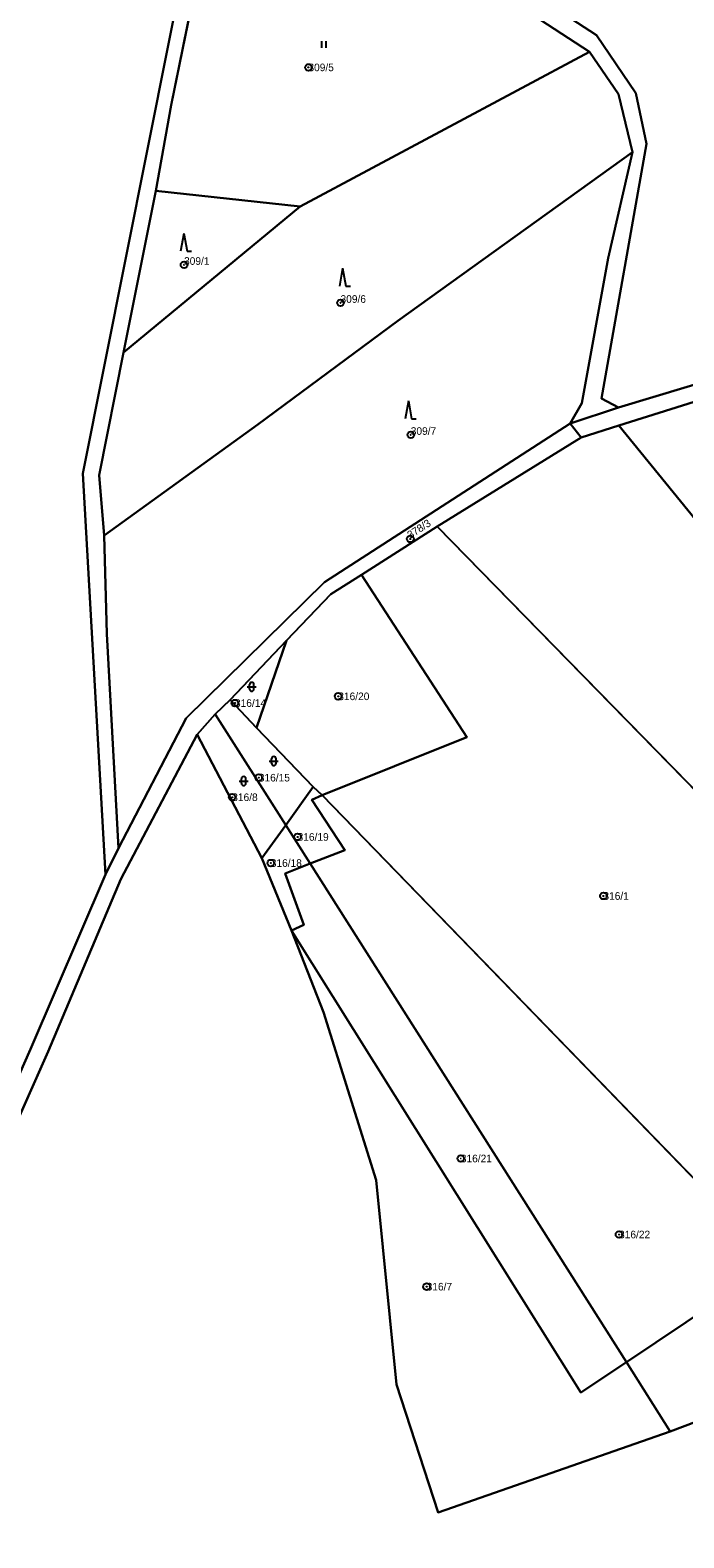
# Model space of a CAD drawing. Extents: x -652854 to -650068, y -1097661 to -1095417.
# Drawn here: x -651296.9 to -651150.7, y -1097423.6 to -1097086.2 of the extents above; entities that cross this region are included whole.
import ezdxf

# ---------------------------------------------------------------- set-up
doc = ezdxf.new("R2010")
doc.units = 0
for name, color, linetype in [('Definiční body parcel', 7, 'Continuous'), ('Hranice parcel', 7, 'Continuous'), ('Obvody jako plochy', 7, 'Continuous'), ('Parcelní čísla', 7, 'Continuous'), ('Značky kultur', 7, 'Continuous')]:
    doc.layers.add(name, color=color, linetype=linetype)

msp = doc.modelspace()

# ---------------------------------------------------------------- linework, layer by layer
at = {"layer": 'Definiční body parcel'}
for centre, radius in [((-651234.63, -1097094.57), 0.75), ((-651234.63, -1097094.57), 0.0327), ((-651262.45, -1097138.74), 0.75), ((-651262.45, -1097138.74), 0.0327), ((-651227.45, -1097147.24), 0.75), ((-651227.45, -1097147.24), 0.0327), ((-651211.74, -1097176.78), 0.75), ((-651211.74, -1097176.78), 0.0327), ((-651211.84, -1097200.07), 0.75), ((-651211.84, -1097200.07), 0.0327), ((-651251.06, -1097236.8), 0.75), ((-651227.95, -1097235.29), 0.75), ((-651227.95, -1097235.29), 0.0327), ((-651251.06, -1097236.8), 0.0327), ((-651245.72, -1097253.49), 0.75), ((-651245.72, -1097253.49), 0.0327), ((-651251.67, -1097257.87), 0.75), ((-651251.67, -1097257.87), 0.0327), ((-651237.05, -1097266.75), 0.75), ((-651237.05, -1097266.75), 0.0327), ((-651243.05, -1097272.59), 0.75), ((-651243.05, -1097272.59), 0.0327), ((-651168.65, -1097279.96), 0.75), ((-651168.65, -1097279.96), 0.0327), ((-651200.54, -1097338.7), 0.75), ((-651200.54, -1097338.7), 0.0327), ((-651165.15, -1097355.71), 0.75), ((-651165.15, -1097355.71), 0.0327), ((-651208.18, -1097367.38), 0.75), ((-651208.18, -1097367.38), 0.0327)]:
    msp.add_circle(centre, radius, dxfattribs=at)
at = {"layer": 'Hranice parcel'}
for p, q in [((-651170.2, -1097087.35), (-651223.1, -1097052.93)), ((-651226.44, -1097055.43), (-651171.74, -1097091.06)), ((-651285.08, -1097185.42), (-651260.99, -1097064.52)), ((-651257.34, -1097063.72), (-651265.36, -1097103.05)), ((-651161.42, -1097100.33), (-651170.2, -1097087.35)), ((-651236.46, -1097125.69), (-651171.74, -1097091.06)), ((-651171.74, -1097091.06), (-651165.29, -1097100.55)), ((-651165.29, -1097100.55), (-651162.11, -1097113.54)), ((-651159.02, -1097111.66), (-651161.42, -1097100.33)), ((-651265.36, -1097103.05), (-651268.78, -1097122.19)), ((-651169.04, -1097168.66), (-651159.02, -1097111.66)), ((-651214.64, -1097151.24), (-651162.11, -1097113.54)), ((-651162.11, -1097113.54), (-651167.56, -1097137.25)), ((-651268.78, -1097122.19), (-651276.03, -1097158.34)), ((-651236.46, -1097125.69), (-651268.78, -1097122.19)), ((-651276.03, -1097158.34), (-651236.46, -1097125.69)), ((-651167.56, -1097137.25), (-651173.47, -1097169.68)), ((-651245.91, -1097174.44), (-651214.64, -1097151.24)), ((-651105.3, -1097152.59), (-651165.31, -1097170.68)), ((-651276.03, -1097158.34), (-651281.45, -1097185.78)), ((-651116.08, -1097159.28), (-651165.19, -1097174.72)), ((-651165.31, -1097170.68), (-651169.04, -1097168.66)), ((-651173.47, -1097169.68), (-651176.11, -1097174.26)), ((-651176.11, -1097174.26), (-651165.31, -1097170.68)), ((-651280.34, -1097199.28), (-651245.91, -1097174.44)), ((-651231.07, -1097209.73), (-651176.11, -1097174.26)), ((-651176.11, -1097174.26), (-651173.63, -1097177.36)), ((-651165.19, -1097174.72), (-651173.63, -1097177.36)), ((-651165.19, -1097174.72), (-651106.75, -1097246.46)), ((-651205.8, -1097197.3), (-651173.63, -1097177.36)), ((-651280.03, -1097275.19), (-651285.08, -1097185.42)), ((-651281.45, -1097185.78), (-651280.34, -1097199.28)), ((-651280.34, -1097199.28), (-651279.74, -1097221.34)), ((-651222.78, -1097208.09), (-651205.8, -1097197.3)), ((-651098.76, -1097306.87), (-651205.8, -1097197.3)), ((-651229.64, -1097212.45), (-651222.78, -1097208.09)), ((-651199.19, -1097244.43), (-651222.78, -1097208.09)), ((-651262.01, -1097240.19), (-651231.07, -1097209.73)), ((-651239.51, -1097222.83), (-651229.64, -1097212.45)), ((-651279.74, -1097221.34), (-651277.09, -1097269.24)), ((-651252.1, -1097236.08), (-651239.51, -1097222.83)), ((-651246.25, -1097242.32), (-651239.51, -1097222.83)), ((-651255.47, -1097239.3), (-651252.1, -1097236.08)), ((-651252.1, -1097236.08), (-651246.25, -1097242.32)), ((-651259.51, -1097243.85), (-651255.47, -1097239.3)), ((-651255.47, -1097239.3), (-651239.71, -1097264.1)), ((-651277.09, -1097269.24), (-651262.01, -1097240.19)), ((-651246.25, -1097242.32), (-651233.58, -1097255.55)), ((-651259.51, -1097243.85), (-651276.57, -1097276.23)), ((-651245.02, -1097271.51), (-651259.51, -1097243.85)), ((-651231.56, -1097257.41), (-651199.19, -1097244.43)), ((-651239.71, -1097264.1), (-651233.58, -1097255.55)), ((-651233.58, -1097255.55), (-651231.56, -1097257.41)), ((-651233.9, -1097258.45), (-651231.56, -1097257.41)), ((-651226.5, -1097269.71), (-651233.9, -1097258.45)), ((-651231.56, -1097257.41), (-651130.24, -1097361.96)), ((-651245.02, -1097271.51), (-651239.71, -1097264.1)), ((-651239.71, -1097264.1), (-651234.23, -1097272.71)), ((-651277.09, -1097269.24), (-651280.03, -1097275.19)), ((-651234.23, -1097272.71), (-651226.5, -1097269.71)), ((-651238.43, -1097287.66), (-651245.02, -1097271.51)), ((-651239.82, -1097274.92), (-651234.23, -1097272.71)), ((-651234.23, -1097272.71), (-651163.51, -1097384.26)), ((-651280.03, -1097275.19), (-651296.82, -1097314.26)), ((-651276.57, -1097276.23), (-651292.83, -1097314.79)), ((-651235.66, -1097286.45), (-651239.82, -1097274.92)), ((-651238.43, -1097287.66), (-651235.66, -1097286.45)), ((-651238.43, -1097287.66), (-651173.71, -1097391.09)), ((-651231.23, -1097305.94), (-651238.43, -1097287.66)), ((-651219.49, -1097343.54), (-651231.23, -1097305.94)), ((-651296.82, -1097314.26), (-651315.05, -1097355.46)), ((-651292.83, -1097314.79), (-651311.99, -1097357.78)), ((-651214.96, -1097389.3), (-651219.49, -1097343.54)), ((-651163.51, -1097384.26), (-651130.24, -1097361.96)), ((-651173.71, -1097391.09), (-651163.51, -1097384.26)), ((-651163.51, -1097384.26), (-651153.69, -1097399.75)), ((-651205.61, -1097417.88), (-651214.96, -1097389.3)), ((-651147.63, -1097397.5), (-651153.69, -1097399.75)), ((-651153.69, -1097399.75), (-651205.61, -1097417.88))]:
    msp.add_line(p, q, dxfattribs=at)
at = {"layer": 'Obvody jako plochy'}
for points in [[(-651105.3, -1097152.59), (-651093.01, -1097103.7), (-651092.42, -1097101.02), (-651110.78, -1097043.06), (-651093.83, -1097038.77), (-651072.08, -1097037.24), (-651052.68, -1097015.8), (-651005.44, -1097024.35), (-650984.81, -1096998.67), (-651046.91, -1096991.17), (-651079.38, -1096986.4), (-651123.24, -1096984.03), (-651223.1, -1097052.93), (-651170.2, -1097087.35), (-651161.42, -1097100.33), (-651159.02, -1097111.66), (-651169.04, -1097168.66), (-651165.31, -1097170.68)], [(-651165.31, -1097170.68), (-651169.04, -1097168.66), (-651159.02, -1097111.66), (-651161.42, -1097100.33), (-651170.2, -1097087.35), (-651223.1, -1097052.93), (-651241.47, -1097030.24), (-651245.41, -1097021.38), (-651247.51, -1097028.99), (-651231.16, -1097049.51), (-651226.44, -1097055.43), (-651171.74, -1097091.06), (-651165.29, -1097100.55), (-651162.11, -1097113.54), (-651167.56, -1097137.25), (-651173.47, -1097169.68), (-651176.11, -1097174.26)], [(-651226.44, -1097055.43), (-651231.16, -1097049.51), (-651257.34, -1097063.72), (-651265.36, -1097103.05), (-651268.78, -1097122.19), (-651236.46, -1097125.69), (-651171.74, -1097091.06)], [(-651171.74, -1097091.06), (-651236.46, -1097125.69), (-651276.03, -1097158.34), (-651281.45, -1097185.78), (-651280.34, -1097199.28), (-651245.91, -1097174.44), (-651214.64, -1097151.24), (-651162.11, -1097113.54), (-651165.29, -1097100.55)], [(-651167.56, -1097137.25), (-651162.11, -1097113.54), (-651214.64, -1097151.24), (-651245.91, -1097174.44), (-651280.34, -1097199.28), (-651279.74, -1097221.34), (-651277.09, -1097269.24), (-651262.01, -1097240.19), (-651231.07, -1097209.73), (-651176.11, -1097174.26), (-651173.47, -1097169.68)], [(-651236.46, -1097125.69), (-651268.78, -1097122.19), (-651276.03, -1097158.34)], [(-650754.48, -1097130.94), (-650799.57, -1097135.85), (-650828.93, -1097134.46), (-650889.89, -1097141.73), (-650904.33, -1097143.45), (-651030.52, -1097124), (-651067.94, -1097138.65), (-651105.3, -1097152.59), (-651165.31, -1097170.68), (-651176.11, -1097174.26), (-651173.63, -1097177.36), (-651165.19, -1097174.72), (-651116.08, -1097159.28), (-651105.93, -1097156.36), (-651071.41, -1097143.63), (-651029.15, -1097127.92), (-650978.61, -1097135.56), (-650909.19, -1097146.38), (-650903.84, -1097147.32), (-650829.16, -1097138.13), (-650798.48, -1097140.15), (-650747.6, -1097136.51)], [(-651116.08, -1097159.28), (-651165.19, -1097174.72), (-651106.75, -1097246.46), (-651096.01, -1097259.99), (-651078.75, -1097281.73), (-651045.37, -1097267.07)], [(-651262.01, -1097240.19), (-651277.09, -1097269.24), (-651280.03, -1097275.19), (-651296.82, -1097314.26), (-651315.05, -1097355.46), (-651352.74, -1097391.59), (-651349.9, -1097394.12), (-651311.99, -1097357.78), (-651292.83, -1097314.79), (-651276.57, -1097276.23), (-651259.51, -1097243.85), (-651255.47, -1097239.3), (-651252.1, -1097236.08), (-651239.51, -1097222.83), (-651229.64, -1097212.45), (-651222.78, -1097208.09), (-651205.8, -1097197.3), (-651173.63, -1097177.36), (-651176.11, -1097174.26), (-651231.07, -1097209.73)], [(-651098.76, -1097306.87), (-651090.59, -1097287.26), (-651078.75, -1097281.73), (-651096.01, -1097259.99), (-651107.78, -1097269.59), (-651133.5, -1097238.3), (-651106.75, -1097246.46), (-651165.19, -1097174.72), (-651173.63, -1097177.36), (-651205.8, -1097197.3)], [(-651116.07, -1097340.17), (-651103.48, -1097317.72), (-651098.76, -1097306.87), (-651205.8, -1097197.3), (-651222.78, -1097208.09), (-651199.19, -1097244.43), (-651231.56, -1097257.41), (-651130.24, -1097361.96), (-651116.32, -1097352.64)], [(-651229.64, -1097212.45), (-651239.51, -1097222.83), (-651246.25, -1097242.32), (-651233.58, -1097255.55), (-651231.56, -1097257.41), (-651199.19, -1097244.43), (-651222.78, -1097208.09)], [(-651252.1, -1097236.08), (-651246.25, -1097242.32), (-651239.51, -1097222.83)], [(-651255.47, -1097239.3), (-651239.71, -1097264.1), (-651233.58, -1097255.55), (-651246.25, -1097242.32), (-651252.1, -1097236.08)], [(-651259.51, -1097243.85), (-651245.02, -1097271.51), (-651239.71, -1097264.1), (-651255.47, -1097239.3)], [(-651239.71, -1097264.1), (-651234.23, -1097272.71), (-651226.5, -1097269.71), (-651233.9, -1097258.45), (-651231.56, -1097257.41), (-651233.58, -1097255.55)], [(-651163.51, -1097384.26), (-651130.24, -1097361.96), (-651231.56, -1097257.41), (-651233.9, -1097258.45), (-651226.5, -1097269.71), (-651234.23, -1097272.71)], [(-651238.43, -1097287.66), (-651235.66, -1097286.45), (-651239.82, -1097274.92), (-651234.23, -1097272.71), (-651239.71, -1097264.1), (-651245.02, -1097271.51)], [(-651238.43, -1097287.66), (-651173.71, -1097391.09), (-651163.51, -1097384.26), (-651234.23, -1097272.71), (-651239.82, -1097274.92), (-651235.66, -1097286.45)], [(-651238.43, -1097287.66), (-651231.23, -1097305.94), (-651219.49, -1097343.54), (-651214.96, -1097389.3), (-651205.61, -1097417.88), (-651153.69, -1097399.75), (-651163.51, -1097384.26), (-651173.71, -1097391.09)], [(-651163.51, -1097384.26), (-651153.69, -1097399.75), (-651147.63, -1097397.5), (-651118.84, -1097373.75), (-651130.24, -1097361.96)]]:
    msp.add_lwpolyline(points, close=True, dxfattribs=at)
for points in [[(-651315.05, -1097355.46), (-651296.82, -1097314.26), (-651280.03, -1097275.19), (-651285.08, -1097185.42), (-651260.99, -1097064.52), (-651294.29, -1097048.39), (-651288.56, -1097037.08), (-651345.79, -1097007.69)], [(-651260.99, -1097064.52), (-651285.08, -1097185.42), (-651280.03, -1097275.19), (-651277.09, -1097269.24), (-651279.74, -1097221.34), (-651280.34, -1097199.28), (-651281.45, -1097185.78), (-651276.03, -1097158.34), (-651268.78, -1097122.19), (-651265.36, -1097103.05), (-651257.34, -1097063.72)], [(-650927.04, -1097439.3), (-650902.09, -1097376.6), (-650898.18, -1097363.61), (-650892.03, -1097352.57), (-650987.01, -1097331.29), (-651014.87, -1097331.26), (-651027.94, -1097369.47), (-651036.09, -1097365.97), (-651087.66, -1097375.14), (-651099.02, -1097367.38), (-651147.63, -1097397.5), (-651153.69, -1097399.75), (-651205.61, -1097417.88), (-651214.96, -1097389.3), (-651219.49, -1097343.54), (-651231.23, -1097305.94), (-651238.43, -1097287.66), (-651245.02, -1097271.51), (-651259.51, -1097243.85), (-651276.57, -1097276.23), (-651292.83, -1097314.79), (-651311.99, -1097357.78)]]:
    msp.add_lwpolyline(points, dxfattribs=at)
at = {"layer": 'Značky kultur'}
for p, q in [((-651231.677, -1097088.705), (-651231.677, -1097090.205)), ((-651230.655, -1097090.205), (-651230.655, -1097088.705)), ((-651262.512, -1097131.709), (-651263.245, -1097135.709)), ((-651262.512, -1097131.709), (-651261.779, -1097135.709)), ((-651261.779, -1097135.709), (-651260.779, -1097135.709)), ((-651226.972, -1097139.489), (-651227.705, -1097143.489)), ((-651226.972, -1097139.489), (-651226.239, -1097143.489)), ((-651226.239, -1097143.489), (-651225.239, -1097143.489)), ((-651212.282, -1097169.179), (-651213.015, -1097173.179)), ((-651212.282, -1097169.179), (-651211.549, -1097173.179)), ((-651211.549, -1097173.179), (-651210.549, -1097173.179)), ((-651248.31, -1097233.16), (-651246.31, -1097233.16)), ((-651247.81, -1097233.66), (-651247.81, -1097232.66)), ((-651246.81, -1097233.66), (-651246.81, -1097232.66)), ((-651243.38, -1097249.77), (-651241.38, -1097249.77)), ((-651242.88, -1097250.27), (-651242.88, -1097249.27)), ((-651241.88, -1097250.27), (-651241.88, -1097249.27)), ((-651250.11, -1097254.25), (-651248.11, -1097254.25)), ((-651249.61, -1097254.75), (-651249.61, -1097253.75)), ((-651248.61, -1097254.75), (-651248.61, -1097253.75))]:
    msp.add_line(p, q, dxfattribs=at)
for centre, start, end in [((-651247.31, -1097232.66), 0, 180), ((-651247.31, -1097233.66), 180, 0), ((-651242.38, -1097249.27), 0, 180), ((-651249.11, -1097253.75), 0, 180), ((-651242.38, -1097250.27), 180, 0), ((-651249.11, -1097254.75), 180, 0)]:
    msp.add_arc(centre, 0.5, start, end, dxfattribs=at)

# ---------------------------------------------------------------- texts
at = {"layer": 'Parcelní čísla'}
for s, p in [('309/5', (-651234.63, -1097095.42)), ('309/1', (-651262.45, -1097138.74)), ('309/6', (-651227.45, -1097147.24)), ('309/7', (-651211.74, -1097176.78)), ('316/14', (-651251.06, -1097237.65)), ('316/20', (-651227.95, -1097236.14)), ('316/15', (-651245.72, -1097254.34)), ('316/8', (-651251.67, -1097258.72)), ('316/19', (-651237.05, -1097267.6)), ('316/18', (-651243.05, -1097273.44)), ('316/1', (-651168.65, -1097280.81)), ('316/21', (-651200.54, -1097339.55)), ('316/22', (-651165.15, -1097356.56)), ('316/7', (-651208.18, -1097368.23))]:
    msp.add_text(s, height=1.7, dxfattribs=at).set_placement(p)
msp.add_text('378/3', height=1.7, rotation=32.76, dxfattribs=at).set_placement((-651211.84, -1097200.07))

doc.saveas('drawing.dxf')
